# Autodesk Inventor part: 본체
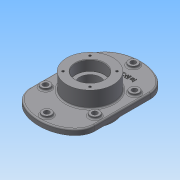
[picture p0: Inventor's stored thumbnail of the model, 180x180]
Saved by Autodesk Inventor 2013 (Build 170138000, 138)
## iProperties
Created: 2015-02
Part Number: 본체
Material: 일반
Document SubType Name: Modeling
Designer: Administrator
Density: 1 g/cm^3
Author: Administrator
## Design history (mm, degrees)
sketch "스케치1" dims "d41" = 50, "d42" = 50
  geometry: L1 (-70, -60)-(70, -60); L2 (70, -60)-(70, 60); L3 (70, 60)-(-70, 60); L4 (-70, 60)-(-70, -60); L5 (-70, -60)-(70, 60); L6 (70, -60)-(-70, 60); 3 further points; 2 other entities
  constraints: 12 end point, 4 midpoint, 3 horizontal, 2 parallel, 1 perpendicular, 8 other
  dimensions: "d0" = 140 distance of L2.end L3.end; "d1" = 120 distance of L2.end L1.end
extrude "돌출1" new body sketch "스케치1" distance "d3" = 12; taper "d4" = 0 deg
node "작업 평면1"
sketch "스케치2"
  geometry: C1 r 50 at (0, 0); 1 further point
  constraints: 1 centre point, 1 coincident
  dimensions: "d6" = 100 diameter of C1
extrude "돌출2" join sketch "스케치2" distance "d7" = 70; taper "d8" = 0 deg
sketch "스케치3"
  geometry: C1 r 50 at (0, 0) reference; C2 r 31 at (0, 0)
  constraints: 1 centre point, 1 coincident
  dimensions: "d9" = 62 diameter of C2
extrude "돌출3" cut sketch "스케치3" distance "d10" = 22; taper "d11" = 0 deg
hole "구멍1" diameter "d14" = 45; stored, may be unused: countersink angle "d18" = 90 deg, drill point angle "d20" = 118 deg; dims "d12" = 10, "d13" = 10, "d15" = 6, "d16" = 62, "d17" = 22, "d19" = 70
fillet "모깎기1" dims "d21" = 3
sketch "스케치4"
  geometry: L1 (0, 0)-(17.779, 0); C1 r 31 at (0, 0) reference; C2 r 50 at (0, 0) reference; 1 further point
  constraints: 2 end point, 1 horizontal
  dimensions: "d22" = 45 deg dimension on C1.centre point (-28.991, 28.991) L1.end; "d23" = 41 distance of point (-28.991, 28.991) C1.centre
hole "구멍2" sketch "스케치4" at (-28.991, 28.991) diameter "d24" = 4.917; stored, may be unused: countersink angle "d28" = 90 deg, drill point angle "d30" = 118 deg; dims "d25" = 10, "d26" = 62, "d27" = 22, "d29" = 13
node "작업 평면2"
fillet "모깎기2" dims "d34" = 0.3
chamfer "모따기1" distance "d35" = 1; stored, may be unused: second distance "d36" = 2, angle "d37" = 45 deg
sketch "스케치5"
  geometry: C1 r 50 at (0, 0) reference; 1 further point
  constraints: 1 vertical alignment, 1 other
  dimensions: "d38" = 65 distance of point (0, 65) C1.centre
feature "엠보싱1" sketch "스케치5" dims "d0" = 140, "d1" = 120, "d20" = 118 deg, "d39" = 1, "d40" = 0, "d41" = 50, "d42" = 50
sketch "스케치6"
  geometry: L1 (-67, -60)-(-67, 60) reference; L2 (67, 60)-(67, -60) reference; L3 (53, 60)-(53, -60); L4 (-53, -60)-(-53, 60); L5 (70, -60)-(70, 60) reference; C1 r 50 at (0, 0) reference; C2 r 10 at (0, 93); C3 r 10 at (-53, 42.733); C4 r 10 at (-53, -42.733); C5 r 10 at (0, -93); C6 r 10 at (53, 42.733); C7 r 10 at (53, -42.733)
  constraints: 6 centre point, 4 end point, 4 point on line, 3 parallel, 2 horizontal alignment, 2 vertical alignment, 8 other
  dimensions: "d43" = 17 distance between parallel lines of L3 L5; "d44" = 20 diameter of C2; "d46" = 20 diameter of C3; "d47" = 20 diameter of C4; "d49" = 85.46667 distance of C4.centre C3.centre; "d50" = 42.73333 vertical distance of C1.centre C3.centre; "d51" = 20 diameter of C5; "d52" = 20 diameter of C6; "d53" = 20 diameter of C7; "d54" = 85.46667 distance of C7.centre C6.centre; "d55" = 42.73333 vertical distance of C6.centre C1.centre
extrude "돌출4" join sketch "스케치6" distance "d56" = 5; taper "d57" = 0 deg
fillet "모깎기3" dims "d58" = 3
fillet "모깎기4" dims "d59" = 3
sketch "스케치7"
  geometry: C1 r 10 at (0, 0) reference; C2 r 10 at (-53, -50.267) reference; C3 r 10 at (-53, -135.733) reference; C4 r 10 at (0, -186) reference; C5 r 10 at (53, -135.733) reference; C6 r 10 at (53, -50.267) reference; 7 further points
  constraints: 6 coincident
hole "구멍3" sketch "스케치7" at (0, 0), (53, -50.267), (-53, -50.267), (-53, -135.733), (0, -186), (53, -135.733) diameter "d60" = 11; stored, may be unused: countersink angle "d64" = 90 deg, drill point angle "d66" = 118 deg; dims "d61" = 10, "d62" = 62, "d63" = 22, "d65" = 20
node "솔리드1"
pattern_circular "원형 패턴1" dims angle "d32" = 360 deg
mirror "대칭1"
node "투영된 루프1"
node "투영된 루프2"
node "투영된 루프3"
node "투영된 루프4"
node "투영된 루프5"
other parameters: "d5" = 23
